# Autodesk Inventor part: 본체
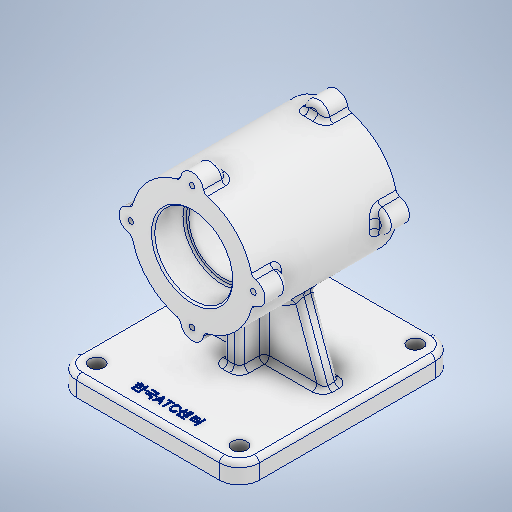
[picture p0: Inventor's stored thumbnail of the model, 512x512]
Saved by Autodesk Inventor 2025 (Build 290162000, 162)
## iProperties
Created: 2024-08
Part Number: 본체
Material: 알루미늄 6061
Document SubType Name: Modeling
Designer: samsung
Density: 2.7 g/cm^3
Appearance: 알루미늄 - 평지
Mass: 1215.39 g
Surface Area: 796.917 cm^2
Volume: 450.145 cm^3
Author: samsung
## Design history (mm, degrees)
sketch "스케치1"
  geometry: L1 (-55, -65)-(55, -65); L2 (55, -65)-(55, 65); L3 (55, 65)-(-55, 65); L4 (-55, 65)-(-55, -65); L5 (-55, -65)-(55, 65); L6 (55, -65)-(-55, 65); 1 further point
  constraints: 12 end point, 2 midpoint, 2 parallel, 1 horizontal, 1 perpendicular
  dimensions: "d0" = 110 distance of L3.end L2.end; "d1" = 130 distance of L2.end L1.end
extrude "돌출1" new body sketch "스케치1" distance "d2" = 12; taper "d3" = 0 deg
node "작업 평면1"
sketch "스케치2"
  geometry: C1 r 37 at (55, 82); 1 further point
  constraints: 1 centre point, 1 vertical alignment
  dimensions: "d5" = 74 diameter of C1; "d6" = 82 distance of point (55, 0) C1.centre
extrude "돌출2" join sketch "스케치2" stored distance "d7" = 87; taper "d8" = 0 deg
sketch "스케치5"
  geometry: C1 r 37 at (0, 0) reference; C2 r 23.5 at (0, 0); 1 further point
  constraints: 1 centre point, 1 coincident
  dimensions: "d23" = 47 diameter of C2
extrude "돌출4" cut sketch "스케치5" distance "d24" = 19; taper "d25" = 0 deg
sketch "스케치6"
  geometry: C1 r 37 at (0, 0) reference; C2 r 23.5 at (0, 0); 1 further point
  constraints: 1 centre point, 1 coincident
  dimensions: "d26" = 47 diameter of C2
extrude "돌출5" cut sketch "스케치6" distance "d27" = 19; taper "d28" = 0 deg
sketch "스케치7"
  geometry: C1 r 23.5 at (0, 0) reference; C2 r 21 at (0, 0); 1 further point
  constraints: 1 centre point, 1 coincident
  dimensions: "d29" = 42 diameter of C2
extrude "돌출6" cut sketch "스케치7" stored distance "d30" = 19; taper "d31" = 0 deg
chamfer "모따기1" distance "d42" = 1; stored, may be unused: second distance "d43" = 2, angle "d44" = 45 deg
fillet "모깎기1" dims "d45" = 12
fillet "모깎기2" dims "d46" = 3
fillet "모깎기3" dims "d47" = 1
sketch "스케치11"
  geometry: L1 (41, 10)-(-41, 10); L2 (-41, 10)-(-41, 0); L3 (-41, 0)-(41, 0); L4 (41, 0)-(41, 10); L5 (41, 10)-(-41, 0); L6 (-41, 10)-(41, 0); L7 (-43, -65)-(43, -65) reference; 2 further points
  constraints: 12 end point, 2 midpoint, 2 parallel, 1 horizontal, 1 perpendicular, 1 vertical alignment
  dimensions: "d63" = 82 distance of L3.end L2.end; "d64" = 10 distance of L2.end L1.end; "d65" = 70 distance from line of L7 point (0, 5)
extrude "돌출8" join sketch "스케치11" distance "d66" = 82; taper "d67" = 0 deg
feature "면 기울기1" dims angle "d68" = 20 deg
sketch "스케치12"
  geometry: L1 (5, 25)-(-5, 25); L2 (-5, 25)-(-5, -15); L3 (-5, -15)-(5, -15); L4 (5, -15)-(5, 25); L5 (5, 25)-(-5, -15); L6 (-5, 25)-(5, -15); L7 (-43, -65)-(43, -65) reference; 2 further points
  constraints: 12 end point, 2 midpoint, 2 parallel, 1 horizontal, 1 perpendicular, 1 vertical alignment
  dimensions: "d69" = 10 distance of L3.end L2.end; "d70" = 40 distance of L2.end L1.end; "d71" = 70 distance from line of L7 point (0, 5)
extrude "돌출9" join sketch "스케치12" distance "d72" = 82; taper "d73" = 0 deg
sketch "스케치13"
  geometry: C1 r 24.5 at (55, 82) reference; C2 r 21 at (55, 82); 1 further point
  constraints: 1 centre point, 1 coincident
  dimensions: "d74" = 42 diameter of C2
extrude "돌출10" cut sketch "스케치13" extent not by distance; stored distance "d75" = 0; taper "d76" = 0 deg
fillet "모깎기4" dims "d77" = 3
fillet "모깎기5" dims "d78" = 3
fillet "모깎기6" dims "d79" = 3
sketch "스케치14"
  geometry: L1 (-43, -65)-(43, -65) reference; L2 (55, -53)-(55, 53) reference; C1 r 4.5 at (43, -53); 1 further point
  constraints: 1 centre point
  dimensions: "d80" = 9 diameter of C1; "d81" = 12 distance from line of L1 C1.centre; "d82" = 12 distance from line of L2 C1.centre
extrude "돌출11" cut sketch "스케치14" stored distance "d83" = 10; taper "d84" = 0 deg
sketch "스케치15"
  geometry: L1 (-43, -65)-(43, -65) reference; 2 further points
  constraints: 1 vertical alignment, 1 other
  dimensions: "d86" = 12 distance from line of L1 point (0, -53)
feature "엠보싱1" sketch "스케치15" dims "d0" = 110, "d1" = 130, "d87" = 0.5, "d88" = 0
sketch "스케치16"
  geometry: C1 r 7 at (37, 0); C2 r 37 at (0, 0) reference; 1 further point
  constraints: 1 centre point, 1 horizontal alignment
  dimensions: "d89" = 14 diameter of C1; "d90" = 37 distance of C1.centre C2.centre
extrude "돌출12" join sketch "스케치16" distance "d91" = 14; taper "d92" = 0 deg
fillet "모깎기8" dims "d96" = 3
fillet "모깎기9" dims "d97" = 3
sketch "스케치17"
  geometry: C1 r 24.5 at (55, 82) reference; A1 r 37 centre (55, 82) between (64.104, 46.138) and (90.862, 72.896) reference; A2 r 3 centre (93.77, 72.158) between (93.239, 75.111) and (90.862, 72.896) reference; A3 r 7 centre (92, 82) between (93.239, 75.111) and (93.239, 88.889) reference; A4 r 3 centre (93.77, 91.842) between (90.862, 91.104) and (93.239, 88.889) reference; A5 r 37 centre (55, 82) between (90.862, 91.104) and (64.104, 117.863) reference; A6 r 3 centre (64.842, 120.77) between (61.889, 120.239) and (64.104, 117.863) reference; A7 r 7 centre (55, 119) between (61.889, 120.239) and (48.111, 120.239) reference; A8 r 3 centre (45.158, 120.77) between (45.896, 117.863) and (48.111, 120.239) reference; A9 r 37 centre (55, 82) between (45.896, 117.863) and (19.137, 91.104) reference; A10 r 3 centre (16.23, 91.842) between (16.761, 88.889) and (19.137, 91.104) reference; A11 r 7 centre (18, 82) between (16.761, 88.889) and (16.761, 75.111) reference; A12 r 3 centre (16.23, 72.158) between (19.137, 72.896) and (16.761, 75.111) reference; A13 r 37 centre (55, 82) between (19.137, 72.896) and (45.896, 46.138) reference; A14 r 3 centre (45.158, 43.23) between (48.111, 43.761) and (45.896, 46.138) reference; A15 r 7 centre (55, 45) between (48.111, 43.761) and (61.889, 43.761) reference; A16 r 3 centre (64.842, 43.23) between (64.104, 46.138) and (61.889, 43.761) reference; 1 further point
hole "구멍2" sketch "스케치17" at (55, 119), (92, 82), (55, 45), (18, 82) diameter "d98" = 3.242; stored, may be unused: countersink angle "d102" = 90 deg, drill point angle "d104" = 118 deg; dims "d99" = 8, "d100" = 4, "d101" = 2, "d103" = 10
node "솔리드1"
mirror "미러3"
mirror "미러4"
pattern_circular "원형 패턴1" dims angle "d94" = 360 deg
mirror "미러5"
mirror "미러7"
node "투영된 루프2"
feature "A9D066F2-1C7D-4E18-AEED-F7BC21143FA4" dims "d98" = 3.242, "d99" = 8, "d100" = 4, "d101" = 2, "d102" = 90 deg, "d103" = 10, "d104" = 118 deg
